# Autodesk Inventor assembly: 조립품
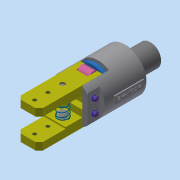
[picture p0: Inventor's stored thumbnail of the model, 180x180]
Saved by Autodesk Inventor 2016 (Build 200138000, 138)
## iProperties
Created: 2019-02
Part Number: 조립품
Material: 일반
Document SubType Name: Assembly
Designer: 3sil_cad0123
Author: 3sil_cad0123
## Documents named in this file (11)
- C:\Users\3sil_cad0123\Desktop\490207V1020\조립품.iam
- C:\Users\3sil_cad0123\Desktop\490207V1020\본체.ipt
- C:\Users\3sil_cad0123\Desktop\490207V1020\E-링.ipt
- C:\Users\3sil_cad0123\Desktop\490207V1020\O-링.ipt
- C:\Users\3sil_cad0123\Desktop\490207V1020\가이드핀.ipt
- C:\Users\3sil_cad0123\Desktop\490207V1020\부시.ipt
- C:\Users\3sil_cad0123\Desktop\490207V1020\스프링.ipt
- C:\Users\3sil_cad0123\Desktop\490207V1020\평행핀 6x28.ipt
- C:\Users\3sil_cad0123\Desktop\490207V1020\피스톤.ipt
- C:\Users\3sil_cad0123\Desktop\490207V1020\핀.ipt
- C:\Users\3sil_cad0123\Desktop\490207V1020\핑거.ipt
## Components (13 placed, 6 different names)
1. E-링:1
2. 가이드핀:1
3. 피스톤:1 — 플러쉬:1
4. 핀:1
5. 핑거:1 — 플러쉬:1
6. 핑거:2
7. E-링:2
8. E-링:4
9. 핀:2
10. E-링:5
11. 가이드핀:2
12. O-링:1
13. O-링:2
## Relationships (1: Flush 1)
- 플러쉬:1 [Flush]: 피스톤:1 ↔ 핑거:1
